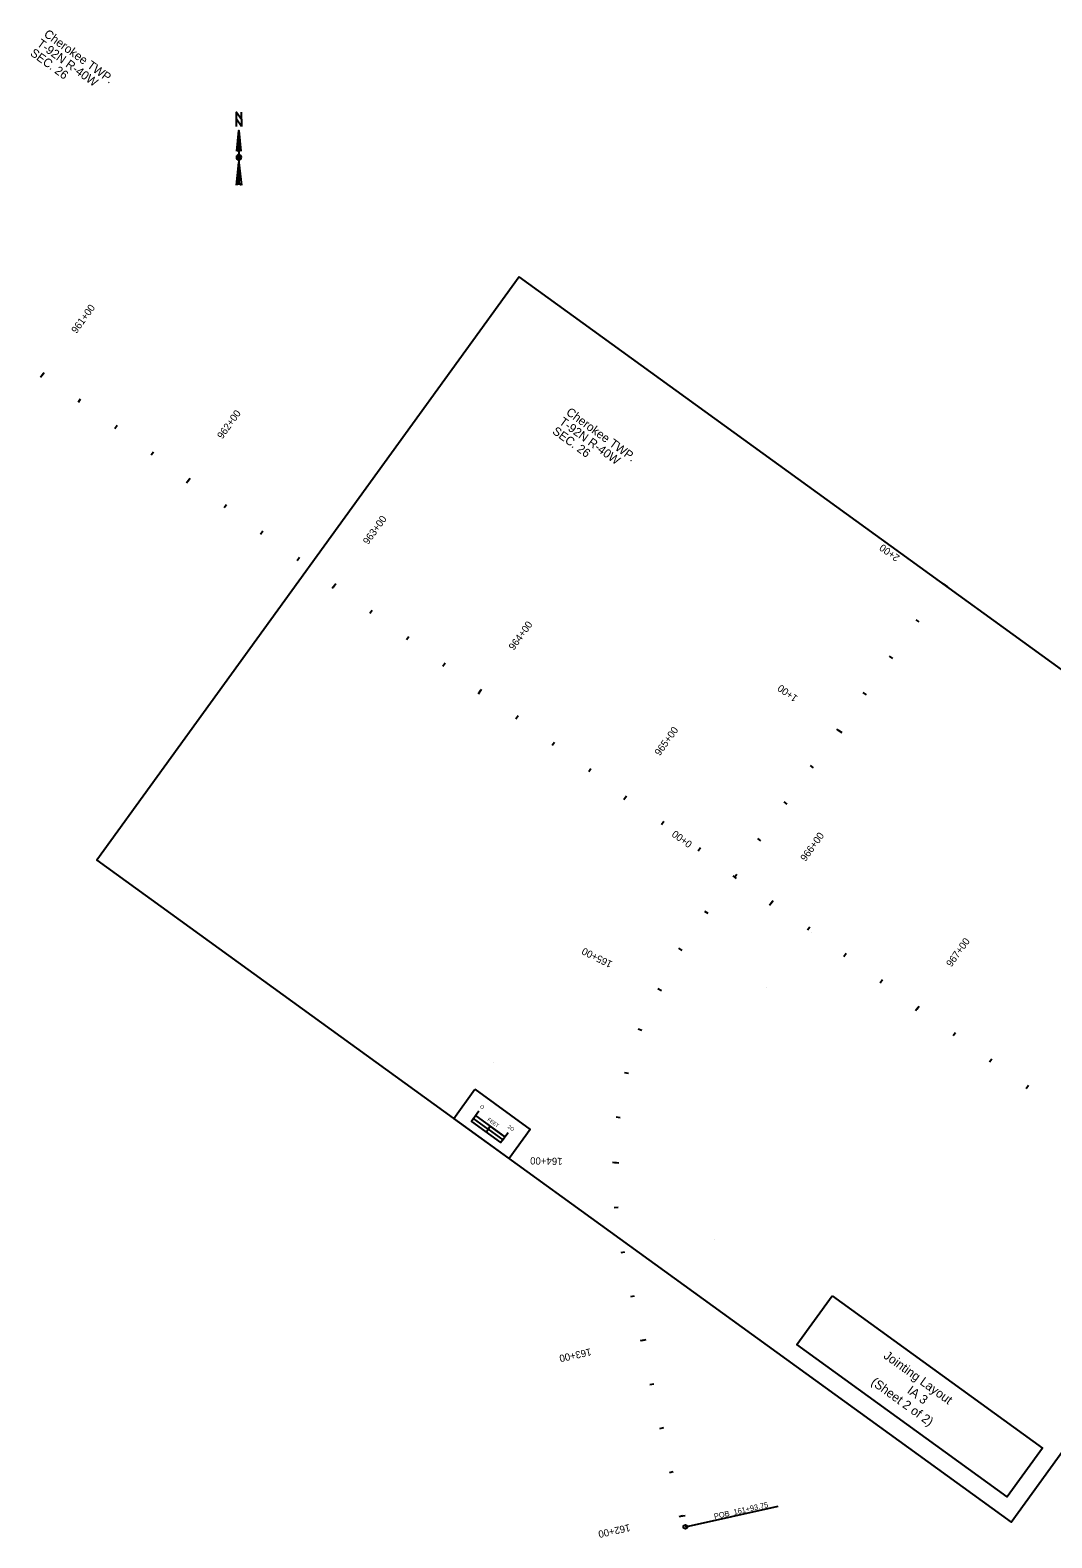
# Model space of a CAD drawing. Extents: x 14311466 to 14314811, y 8682098 to 8684603.
# Drawn here: x 14313728 to 14314296, y 8682335 to 8683172 of the extents above; entities that cross this region are included whole.
import ezdxf

# ---------------------------------------------------------------- set-up
doc = ezdxf.new("R2010")
doc.units = 0
for name, color, linetype in [('Cell', 7, 'Continuous'), ('Draft_8', 7, 'Continuous'), ('NamedBoundary', 7, 'Continuous'), ('SheetText', 7, 'Continuous'), ('Text', 7, 'Continuous'), ('TextAlignment', 7, 'Continuous'), ('TextAlignmentLrg', 7, 'Continuous'), ('TextAlignmentSml', 7, 'Continuous')]:
    doc.layers.add(name, color=color, linetype=linetype)

msp = doc.modelspace()

# ---------------------------------------------------------------- linework, layer by layer
at = {"layer": 'Cell'}
for p, q in [((14313844.43, 8683116.2), (14313845.57, 8683104.79)), ((14313844.43, 8683116.2), (14313844.43, 8683086.53)), ((14313843.28, 8683104.79), (14313843.28, 8683104.79)), ((14313843.33, 8683104.89), (14313843.54, 8683105.13)), ((14313843, 8683085.96), (14313844.43, 8683098.51)), ((14313844.43, 8683099.94), (14313844.43, 8683099.94))]:
    msp.add_line(p, q, dxfattribs=at)
msp.add_lwpolyline([(14313845.85, 8683118.48), (14313843, 8683122.47), (14313843, 8683126.46), (14313845.85, 8683122.47)], close=True, dxfattribs=at)
for points in [[(14313843, 8683118.48), (14313843, 8683126.46), (14313845.85, 8683122.47), (14313845.85, 8683126.46)], [(14313843.28, 8683104.79), (14313844.43, 8683116.2), (14313844.43, 8683105.36)], [(14313845.85, 8683101.36), (14313844.43, 8683101.36), (14313844.43, 8683102.79)], [(14313844.43, 8683099.94), (14313844.43, 8683101.36), (14313843, 8683101.36)], [(14313844.43, 8683086.53), (14313844.43, 8683098.51), (14313845.85, 8683085.96)]]:
    msp.add_lwpolyline(points, dxfattribs=at)
for centre, radius, start, end in [((14313844.43, 8683101.36), 1.43, 90, 180), ((14313844.43, 8683103.93), 1.43, 90.02039, 143.12574), ((14313844.43, 8683103.93), 1.43, 36.84806, 90.02184), ((14313844.43, 8683101.36), 1.43, 0, 90), ((14313844.43, 8683101.36), 1.43, 180, 270), ((14313844.43, 8683101.36), 1.43, 270, 360), ((14313844.42, 8683084.47), 2.07, 89.98939, 133.61895), ((14313844.43, 8683084.46), 2.07, 46.40206, 90.00064)]:
    msp.add_arc(centre, radius, start, end, dxfattribs=at)
at = {"layer": 'Draft_8'}
msp.add_lwpolyline([(14314173.97, 8682469.08), (14314290.8, 8682384.48), (14314271.14, 8682357.32), (14314154.3, 8682441.91)], close=True, dxfattribs=at)
at = {"layer": 'NamedBoundary'}
msp.add_lwpolyline([(14314000.1, 8683035.05), (14313765.51, 8682711.06), (14314273.37, 8682343.35), (14314507.95, 8682667.35)], close=True, dxfattribs=at)
at = {"layer": 'SheetText'}
msp.add_line((14313981.7, 8682559.97), (14313984.05, 8682563.21), dxfattribs=at)
msp.add_line((14313981.7, 8682559.97), (14313984.05, 8682563.21), dxfattribs=at)
for points in [[(14313975.46, 8682583.74), (14314006.24, 8682561.46), (14313994.51, 8682545.26), (14313963.73, 8682567.54)], [(14313975.46, 8682583.74), (14314006.24, 8682561.46), (14313994.51, 8682545.26), (14313963.73, 8682567.54)], [(14313973.6, 8682565.83), (14313981.7, 8682559.97), (14313982.88, 8682561.6), (14313974.78, 8682567.46)], [(14313982.88, 8682561.6), (14313990.98, 8682555.73), (14313992.15, 8682557.34), (14313984.05, 8682563.21)]]:
    msp.add_lwpolyline(points, close=True, dxfattribs=at)
for points in [[(14313977.71, 8682571.5), (14313973.6, 8682565.83), (14313989.8, 8682554.1), (14313993.91, 8682559.77)], [(14313975.95, 8682569.07), (14313992.15, 8682557.34)]]:
    msp.add_lwpolyline(points, dxfattribs=at)
at = {"layer": 'TextAlignment'}
for p, q in [((14314162.49, 8682670.55), (14314162.49, 8682670.55)), ((14314137.74, 8682640.46), (14314137.74, 8682640.46)), ((14313985.92, 8682598.84), (14313985.92, 8682598.84)), ((14314108.69, 8682500.31), (14314108.69, 8682500.31)), ((14314092.43, 8682340.7), (14314143.98, 8682352.12)), ((14314143.98, 8682352.12), (14314143.98, 8682352.12))]:
    msp.add_line(p, q, dxfattribs=at)
msp.add_circle((14314092.43, 8682340.7), 1.07, dxfattribs=at)
at = {"layer": 'TextAlignmentLrg'}
for p, q in [((14313734.98, 8682980.09), (14313736.26, 8682981.86)), ((14313815.98, 8682921.44), (14313817.26, 8682923.21)), ((14313896.98, 8682862.8), (14313898.26, 8682864.56)), ((14314237.02, 8682863.52), (14314235.25, 8682864.8)), ((14313977.98, 8682804.15), (14313979.26, 8682805.92)), ((14314178.37, 8682782.52), (14314176.6, 8682783.8)), ((14314059.69, 8682746.5), (14314058.26, 8682744.51)), ((14314118.73, 8682702.24), (14314120.72, 8682700.8)), ((14314139.97, 8682686.86), (14314141.25, 8682688.63)), ((14314077.08, 8682639.75), (14314079.27, 8682638.65)), ((14314220.97, 8682628.21), (14314222.25, 8682629.98)), ((14314054.22, 8682542.96), (14314052.03, 8682543.01)), ((14314069.45, 8682444.44), (14314067.32, 8682443.96)), ((14314091.08, 8682346.8), (14314088.94, 8682346.33))]:
    msp.add_line(p, q, dxfattribs=at)
at = {"layer": 'TextAlignmentSml'}
for p, q in [((14313735.7, 8682981.08), (14313734.27, 8682979.1)), ((14313755.23, 8682965.43), (14313756.51, 8682967.19)), ((14313775.48, 8682950.76), (14313776.76, 8682952.53)), ((14313795.73, 8682936.1), (14313797.01, 8682937.87)), ((14313816.7, 8682922.43), (14313815.26, 8682920.45)), ((14313836.23, 8682906.78), (14313837.51, 8682908.55)), ((14313856.48, 8682892.12), (14313857.76, 8682893.89)), ((14313876.73, 8682877.46), (14313878.01, 8682879.23)), ((14313897.7, 8682863.79), (14313896.26, 8682861.8)), ((14314236.02, 8682864.23), (14314238.01, 8682862.8)), ((14313917.23, 8682848.13), (14313918.51, 8682849.9)), ((14314222.35, 8682843.27), (14314220.59, 8682844.55)), ((14313937.48, 8682833.47), (14313938.76, 8682835.24)), ((14313957.73, 8682818.81), (14313959.01, 8682820.58)), ((14314207.69, 8682823.02), (14314205.92, 8682824.3)), ((14313978.7, 8682805.14), (14313977.26, 8682803.16)), ((14314193.03, 8682802.77), (14314191.26, 8682804.05)), ((14313998.23, 8682789.49), (14313999.51, 8682791.26)), ((14314018.48, 8682774.83), (14314019.76, 8682776.6)), ((14314177.38, 8682783.24), (14314179.36, 8682781.8)), ((14314038.73, 8682760.17), (14314040.01, 8682761.93)), ((14314163.71, 8682762.27), (14314161.94, 8682763.55)), ((14314059.69, 8682746.5), (14314058.26, 8682744.51)), ((14314149.05, 8682742.02), (14314147.28, 8682743.3)), ((14314079.23, 8682730.84), (14314080.51, 8682732.61)), ((14314099.47, 8682716.18), (14314100.76, 8682717.95)), ((14314134.39, 8682721.77), (14314132.62, 8682723.05)), ((14314118.73, 8682702.24), (14314120.72, 8682700.8)), ((14314119.72, 8682701.52), (14314121.01, 8682703.29)), ((14314140.69, 8682687.85), (14314139.26, 8682685.87)), ((14314105.06, 8682681.27), (14314103.29, 8682682.55)), ((14314160.22, 8682672.2), (14314161.5, 8682673.97)), ((14314090.63, 8682660.86), (14314088.8, 8682662.06)), ((14314180.47, 8682657.54), (14314181.75, 8682659.3)), ((14314200.72, 8682642.87), (14314202, 8682644.64)), ((14314077.08, 8682639.75), (14314079.27, 8682638.65)), ((14314221.69, 8682629.2), (14314220.25, 8682627.22)), ((14314068.2, 8682616.29), (14314066.15, 8682617.05)), ((14314241.22, 8682613.55), (14314242.5, 8682615.32)), ((14314261.47, 8682598.89), (14314262.75, 8682600.66)), ((14314060.83, 8682592.42), (14314058.71, 8682592.94)), ((14314281.72, 8682584.23), (14314283, 8682586)), ((14314056.15, 8682567.87), (14314053.98, 8682568.16)), ((14314052.99, 8682542.99), (14314055.44, 8682542.93)), ((14314055.06, 8682517.99), (14314052.88, 8682517.79)), ((14314058.67, 8682493.26), (14314056.53, 8682492.83)), ((14314064.04, 8682468.85), (14314061.91, 8682468.37)), ((14314068.25, 8682444.17), (14314070.64, 8682444.7)), ((14314074.86, 8682420.03), (14314072.72, 8682419.56)), ((14314080.26, 8682395.62), (14314078.13, 8682395.15)), ((14314085.67, 8682371.21), (14314083.54, 8682370.74)), ((14314089.88, 8682346.54), (14314092.27, 8682347.07))]:
    msp.add_line(p, q, dxfattribs=at)

# ---------------------------------------------------------------- texts
at = {"layer": 'Draft_8'}
for s, p in [('Jointing Layout', (14314202.09, 8682434.81)), ('(Sheet 2 of 2)', (14314195.13, 8682420.09)), ('IA 3', (14314215.22, 8682415.42))]:
    msp.add_text(s, height=5, rotation=324.09397, dxfattribs=at).set_placement(p)
at = {"layer": 'SheetText'}
for s, p in [('O', (14313978.08, 8682573.7)), ('FEET', (14313982.24, 8682566.49)), ('2O', (14313993.56, 8682562.49))]:
    msp.add_text(s, height=2, rotation=324.09397, dxfattribs=at).set_placement(p)
at = {"layer": 'Text'}
for s, p in [('Cherokee TWP.', (14313735.69, 8683168.91)), ('SEC. 26', (14313728.05, 8683158.35)), ('T-92N R-40W', (14313731.84, 8683163.59)), ('Cherokee TWP.', (14314025.78, 8682958.87)), ('T-92N R-40W', (14314021.94, 8682953.56)), ('SEC. 26', (14314018.14, 8682948.31))]:
    msp.add_text(s, height=4.8, rotation=324.0943, dxfattribs=at).set_placement(p)
at = {"layer": 'TextAlignment'}
for s, p in [('POB ', (14314108.69, 8682344.97)), ('161+93.75', (14314119.51, 8682347.37))]:
    msp.add_text(s, height=3, rotation=12.49003, dxfattribs=at).set_placement(p)
at = {"layer": 'TextAlignmentLrg'}
for s, rotation, p in [('965+00', 54.09397, (14314078.19, 8682768.63)), ('0+00', 144.09397, (14314096.6, 8682720.74)), ('165+00', 153.28924, (14314052.28, 8682654.48))]:
    msp.add_text(s, height=4.008, rotation=rotation, dxfattribs=at).set_placement(p)
at = {"layer": 'TextAlignmentSml'}
for s, rotation, p in [('961+00', 54.09397, (14313754.2, 8683003.21)), ('962+00', 54.09397, (14313835.2, 8682944.57)), ('963+00', 54.09397, (14313916.2, 8682885.92)), ('2+00', 144.09397, (14314211.86, 8682879.74)), ('964+00', 54.09397, (14313997.19, 8682827.27)), ('1+00', 144.09397, (14314155.25, 8682801.73)), ('965+00', 54.09397, (14314078.19, 8682768.63)), ('966+00', 54.09397, (14314159.19, 8682709.98)), ('967+00', 54.09397, (14314240.19, 8682651.34)), ('165+00', 153.28924, (14314052.28, 8682654.48)), ('164+00', 178.75403, (14314024.27, 8682545.61)), ('163+00', 192.49003, (14314039.73, 8682439.91)), ('162+00', 192.49003, (14314061.35, 8682342.27))]:
    msp.add_text(s, height=4.008, rotation=rotation, dxfattribs=at).set_placement(p)

doc.saveas('drawing.dxf')
